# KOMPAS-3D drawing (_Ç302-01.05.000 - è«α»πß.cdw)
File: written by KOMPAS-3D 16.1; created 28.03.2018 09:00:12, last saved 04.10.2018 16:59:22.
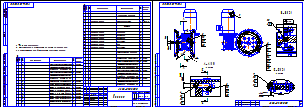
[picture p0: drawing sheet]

Sheets 1-2: A3, landscape

Title block, sheet 1: name: Корпус; designation: А302-01.05.000; mass: 34,05; scale: 1:4; sheet number: 1; sheets: 2; organisation: ЗАО «Астерион»; sheet format: A3; stored path: Z:\Мембранные насосы\Мембранный электропривод\А302-00.00.000 - ASTRA-302 (МЭ200)\Чертежи\А302-00.05.000 - Корпус.cdw; drawn by: Милов; technical control: Лучихин
Title block, sheet 2: sheet number: 2; stored path: Z:\Мембранные насосы\Мембранный электропривод\А302-00.00.000 - ASTRA-302 (МЭ200)\3Д ПВХ\А302-01.05.000 - Корпус.cdw

Views: Разрез А-А, Разрез Б-Б, Разрез В-В
Referenced files in \\192.168.87.28\Konstructor_doc\Мембранные насосы\Мембранный электропривод\А302-00.00.000 - ASTRA-302 (МЭ200)\3Д ПВХ\Отработка\: А302-01.05.000 - Корпус.a3d, Упор-1.m3d, А302-01.20.000 - Мотор-редуктор.a3d, А302-01.05.002 - Ловитель.m3d, Фиксатор.m3d
Referenced files in \\192.168.87.28\Konstructor_doc\Мембранные насосы\Мембранный электропривод\А302-00.00.000 - ASTRA-302 (МЭ200)\3Д\: А302-00.20.004 - Вал.m3d, А302-00.35.001 - Труба 140х140х4.m3d, А302-00.35.002 - Пластина.m3d, А302-00.20.003 - Ползун.m3d
Referenced files in \\192.168.87.28\Konstructor_doc\Мембранные насосы\Мембранный электропривод\А302-00.00.000 - ASTRA-302 (МЭ200)\3Д ПВХ\: А302-01.05.012 - Фиксатор.m3d, А302-01.05.011 - Ловитель.m3d, А302-01.05.002 - Ловитель.cdw, А302-01.05.001 - Основание.cdw, А302-01.05.012 - Фиксатор.cdw, А302-01.05.014 - Упор.cdw, А302-01.05.011 - Ловитель.cdw, А302-01.05.015 - Фиксатор.cdw, А302-01.20.001 - Основание.m3d, А302-01.35.000 - Фланец.a3d, А302-01.20.002 - Эксцентрик.m3d, А302-01.05.001 - Основание.m3d, А302-01.05.015 - Фиксатор.m3d
Referenced files in \\192.168.87.28\Konstructor_doc\1 ПКИ 3D\Редуктора NMRW\Редукторы\: Редуктор NMRW 063.m3d, Червячный мотор-редуктор NMRV063 АИР80.a3d
Referenced files in C:\Program Files\ASCON\KOMPAS-3D V16\Libs\PartLib\DATA\vault\Methods\Kompas\3D\: PLib_Washer_2_712.m3d, PLib_Washer_1_712.m3d, PLib_Screw_DIN_7984_1500.m3d, PLib_Check_spring_rings_GOST_13942_911.m3d, PLib_Nut_OST92_900.m3d, PLib_Key_prismatic_712.m3d, PLib_Screw_ISO_10642_1500.m3d
Referenced files in Z:\Мембранные насосы\Мембранный электропривод\А302-00.00.000 - ASTRA-302 (МЭ200)\3Д ПВХ\: А302-01.20.000 - Мотор-редуктор.cdw
Referenced files: GRAPHIC.TDP
Referenced files in \\192.168.87.28\Konstructor_doc\1 ПКИ 3D\Двигатели\АИР\: Электродвигатель АИР 80А4 IM 3081 1,1кВт 1400 об..m3d
Referenced files in \\192.168.87.28\Konstructor_doc\1 ПКИ 3D\1 Крепеж стандартный\Подшипник\: Подшипник 52х25х15 62052RSH SKF.m3d, Подшипник 80х40х18 6208-2RS1 SKF.m3d
Referenced files in C:\Program Files\ASCON\KOMPAS-3D V16\Libs\PartLib\DATA\VAULT\Methods\kompas\3d\: PLib_Bolt_1_900.m3d
Referenced files in Z:\Мембранные насосы\Мембранный электропривод\А302-00.00.000 - ASTRA-302 (МЭ200)\3Д\: А302-00.20.002 - Эксцентрик.m3d
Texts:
  *Размеры для справок.
  Фиксатор поз.5 установить по месту см. разрез В-В.
  Винт потай М4 поз.9 стопорить краской в резьбу.
  Мотор-редуктор
  @100~)2xA3
  Ловитель
  Основание
  Шайба C.8.21 ГОСТ 11371-78
  Крепежное изделие ГОСТ
  Шайба
  ГОСТ
  нерж.
  Сталь 12Х18Н10Т ГОСТ 5632-72
  Шайба C 8 ГОСТ 6958-78
  Сталь 20 ГОСТ 1050-2013
  Шайба C 8.04.019 ГОСТ 6958-78
  Шайба 8 ГОСТ 6402-70
  Сталь 30Х13 ГОСТ 5632-72
  Шайба 8 30Х13 019 ГОСТ 6402-70
  Болт М8-6gx30 ГОСТ 7805-70
  Болт
  Болт М8-6gx30.58.019 ГОСТ 7805-70
  Гайка М8-6H ГОСТ 5915-70
  Гайка
  Гайка М8-6H.5.019 ГОСТ 5915-70
  Подшипник 80х40х18 6208-2RS1 SKF
  Подшипник
  SKF
  Фиксатор
  Упор
  Шайба C.5.21 ГОСТ 11371-78
  Шайба 5 ГОСТ 6402-70
  Винт с цилиндрической головкой
  и шестигранным углублением под ключ
  ГОСТ Р ИСО  4762-М5 x 16
  Винт с цилиндрической головкой и шестигранным углублением под ключ
  Р ИСО
  Сталь
  Шайба 5 30Х13 019 ГОСТ 6402-70
  Винт с цилиндрической головкой и шестигранным углублением под ключ ГОСТ Р ИСО  4762-М5 x 16-6.8-A9J
  ГОСТ Р ИСО  4762-М5 x 12
  Винт с цилиндрической головкой и шестигранным углублением под ключ ГОСТ Р ИСО  4762-М5 x 12-6.8-A9J
  Винт с потайной головкой
  ГОСТ Р ИСО  10642-М4 x 20
  Винт с потайной головкой и шестигранным углублением под ключ
  Винт с потайной головкой и шестигранным углублением под ключ ГОСТ Р ИСО  10642-М4 x 20-8.8-A3J
  ГОСТ Р ИСО  4762-М8 x 45
  Винт с цилиндрической головкой и шестигранным углублением под ключ ГОСТ Р ИСО  4762-М8 x 45-6.8-A9J
  ГОСТ Р ИСО  4762-М8 x 35
  Винт с цилиндрической головкой и шестигранным углублением под ключ ГОСТ Р ИСО  4762-М8 x 35-6.8-A9J
  Кольцо A40.65Г ГОСТ 13942-86
  Кольцо
  Сталь 65Г ГОСТ 14959-79
  Лит-Масса-Масштаб
  Материал-Предприятие
  Title Specification
  Body Specification ( left align )
  Body Specificaton ( centered )
  Поз.
  Кол.
  Приме-
  чание
  Таблица спецификации
  Электродвигатель АИР 80А4 IM 3081 1,1кВт 1400 об.
  Редуктор NMRW 063
  Червячный мотор-редуктор NMRV063 АИР80
  Пластина
  Труба 140х140х4
  Фланец
  Эксцентрик
  Кольцо A25.65Г ГОСТ 13942-86
  Подшипник 52х25х15 62052RSH SKF
  Вал
  Ползун
  Шайба C.5.04.019 ГОСТ 11371-78
  Болт М5-6gx35.58.019 ГОСТ 7805-70
  Гайка М5-6H.5.019 ГОСТ 5915-70
  Винт с цилиндрической головкой и шестигранным углублением под ключ ГОСТ Р ИСО 4762 - М8 x 25 - A2-70
  Винт с цилиндрической головкой и шестигранным углублением под ключ ГОСТ Р ИСО 4762 - М8 x 35 - A2-70
  Гайка М8-6H.21.12Х18Н10Т ГОСТ 5915-70
  Шпонка 8x7x90 ГОСТ 23360-78
  Винт с цилиндрической головкой и шестигранным углублением под ключ ГОСТ Р ИСО 4762 - М5 x 16 - 6.8 - A9J
  Винт с цилиндрической головкой и шестигранным углублением под ключ ГОСТ Р ИСО 4762 - М5 x 12 - 6.8 - A9J
  Винт с потайной головкой и шестигранным углублением под ключ ГОСТ Р ИСО 10642 - М4 x 20 - 8.8 - A3J
  Винт с цилиндрической головкой и шестигранным углублением под ключ ГОСТ Р ИСО 4762 - М8 x 45 - 6.8 - A9J
  Винт с цилиндрической головкой и шестигранным углублением под ключ ГОСТ Р ИСО 4762 - М8 x 35 - 6.8 - A9J
Dimensions and other numbers on the sheet: 4 места; 9; 4; 11; 16; 19; 6; 12; 17; 20; 1; 3; 2; 21; 40Х; 019; 18; 8; 04; 58; 30Х13; 14; 5; 6.8; 10; 8.8; 13; 15; 65Г; 7; 1:4; 34,05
